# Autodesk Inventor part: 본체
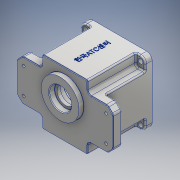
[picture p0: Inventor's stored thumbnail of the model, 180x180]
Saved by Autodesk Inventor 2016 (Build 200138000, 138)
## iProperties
Created: 2017-01
Part Number: 본체
Material: 알루미늄 6061
Document SubType Name: Modeling
Designer: Owner
Mass: 876.679 g
Surface Area: 765.057 cm^2
Volume: 324.696 cm^3
Density: 2.7 g/cm^3
Appearance: 알루미늄 - 평지
Author: Owner
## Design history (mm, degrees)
sketch "스케치1"
  geometry: L1 (70, -30)-(-70, -30); L2 (-70, -30)-(-70, 30); L3 (-70, 30)-(70, 30); L4 (70, 30)-(70, -30); L5 (70, -30)-(-70, 30); L6 (-70, -30)-(70, 30); 1 further point
  constraints: 12 end point, 2 midpoint, 2 parallel, 1 horizontal, 1 perpendicular
  dimensions: "d0" = 140 distance of L2.end L3.end; "d1" = 60 distance of L1.end L2.end
extrude "돌출1" new body sketch "스케치1" distance "d2" = 13; taper "d3" = 0 deg
sketch "스케치2"
  geometry: L1 (-47, -47)-(47, -47); L2 (47, -47)-(47, 47); L3 (47, 47)-(-47, 47); L4 (-47, 47)-(-47, -47); L5 (-47, -47)-(47, 47); L6 (47, -47)-(-47, 47); 1 further point
  constraints: 12 end point, 2 midpoint, 2 parallel, 1 horizontal, 1 perpendicular
  dimensions: "d4" = 94 distance of L3.end L2.end; "d5" = 94 distance of L2.end L1.end
extrude "돌출2" join sketch "스케치2" distance "d6" = 80; taper "d7" = 0 deg
sketch "스케치3"
  geometry: L1 (-47, 30)-(-33, 30); L2 (-33, 30)-(-33, 47); L3 (-33, 47)-(-47, 47); L4 (-47, 47)-(-47, 30); L5 (-47, 30)-(-33, 47); L6 (-33, 30)-(-47, 47); 3 further points
  constraints: 12 end point, 2 midpoint, 2 parallel, 1 coincident, 1 horizontal, 1 perpendicular
  dimensions: "d8" = 14 distance of L2.end L3.end; "d9" = 17 distance of L3.end L1.start
extrude "돌출3" cut sketch "스케치3" distance "d10" = 70; taper "d11" = 0 deg
sketch "스케치4"
  geometry: L1 (0, 0)-(80, 0); L2 (80, -47)-(80, 47) reference; L3 (80, 0)-(80, 43); L4 (71, 43)-(71, 40); L5 (71, 40)-(9, 40); L6 (9, 40)-(9, 0); L7 (71, 43)-(80, 43)
  constraints: 12 end point, 3 perpendicular, 2 point on line, 1 midpoint
  dimensions: "d12" = 86 diameter of L7 L1; "d13" = 80 diameter of L5 L1; "d14" = 9 distance of L4.start L3.end; "d15" = 71 distance between parallel lines of L2 L6
revolve "회전2" sketch "스케치4" stored, may be unused: angle "d17" = 90 deg
sketch "스케치5"
  geometry: A1 r 21 centre (0, -11) between (-8.978, 7.984) and (8.978, 7.984); A2 r 15 centre (0, 20) between (8.978, 7.984) and (-8.978, 7.984); 1 further point
  constraints: 4 point on circle, 2 centre point, 2 vertical alignment
  dimensions: "d18" = 11 distance of A1.centre point (0, 0); "d19" = 20 distance of point (0, 0) A2.centre; "d20" = 42 diameter of A1; "d21" = 30 diameter of A2
extrude "돌출4" join sketch "스케치5" distance "d22" = 7; taper "d23" = 0 deg
sketch "스케치6"
  geometry: A1 r 4 centre (36, 0) between (35.852, 3.997) and (35.852, -3.997); A2 r 40 centre (0, 0) between (39.148, -8.214) and (39.148, 8.214) reference; A3 r 3.5 centre (35.722, -7.495) between (39.148, -8.214) and (35.852, -3.997); A4 r 3.5 centre (35.722, 7.495) between (35.852, 3.997) and (39.148, 8.214); 1 further point
  constraints: 8 point on circle, 4 tangent, 3 centre point, 1 horizontal alignment
  dimensions: "d24" = 8 diameter of A1; "d25" = 36 distance of point (0, 0) A1.centre; "d28" = 7 diameter of A3; "d29" = 7 diameter of A4
extrude "돌출6" join sketch "스케치6" stored distance "d30" = 7; taper "d31" = 0 deg
hole "구멍1" diameter "d34" = 19; stored, may be unused: countersink angle "d38" = 90 deg, drill point angle "d40" = 0 deg; dims "d32" = 10, "d33" = 10, "d35" = 6, "d36" = 22, "d37" = 7, "d39" = 8
hole "구멍2" diameter "d43" = 25; stored, may be unused: countersink angle "d47" = 90 deg, drill point angle "d49" = 0 deg; dims "d41" = 10, "d42" = 10, "d44" = 6, "d45" = 35, "d46" = 10, "d48" = 8
sketch "스케치7"
  geometry: C1 r 27.5 at (0, 11); C2 r 12.5 at (0, 11) reference; 1 further point
  constraints: 1 centre point, 1 concentric
  dimensions: "d50" = 55 diameter of C1
extrude "돌출7" join sketch "스케치7" distance "d51" = 7; taper "d52" = 0 deg
hole "구멍3" diameter "d55" = 32; stored, may be unused: countersink angle "d59" = 90 deg, drill point angle "d61" = 0 deg; dims "d56" = 6, "d57" = 35, "d58" = 10, "d60" = 8, "d126" = 10, "d127" = 10
fillet "모깎기1" dims "d62" = 8
sketch "스케치8"
  geometry: 2 further points
  dimensions: "d63" = 40 horizontal distance of point (40, 40) point (0, 0); "d64" = 40 horizontal distance of point (0, 0) point (40, 40)
hole "구멍4" sketch "스케치8" at (40, 40) diameter "d65" = 7; stored, may be unused: countersink angle "d69" = 90 deg, drill point angle "d71" = 0 deg; dims "d66" = 6, "d67" = 35, "d68" = 10, "d70" = 7
sketch "스케치9"
  geometry: 2 further points
  dimensions: "d78" = 19 vertical distance of point (0, 0) point (60, 19); "d79" = 60 horizontal distance of point (0, 0) point (60, 19)
hole "구멍5" sketch "스케치9" at (60, 19) diameter "d80" = 4; stored, may be unused: countersink angle "d84" = 90 deg, drill point angle "d86" = 0 deg; dims "d81" = 6, "d82" = 10, "d83" = 4, "d85" = 7
chamfer "모따기1" distance "d93" = 1; stored, may be unused: second distance "d94" = 2, angle "d95" = 45 deg
hole "구멍6" diameter "d98" = 3.242; stored, may be unused: countersink angle "d102" = 90 deg, drill point angle "d104" = 118 deg; dims "d96" = 10, "d97" = 10, "d99" = 7, "d100" = 10, "d101" = 4, "d103" = 9
fillet "모깎기2" dims "d105" = 3
fillet "모깎기3" dims "d106" = 2
fillet "모깎기4" dims "d107" = 2
fillet "모깎기5" dims "d108" = 0.3
chamfer "모따기2" distance "d109" = 1; stored, may be unused: second distance "d110" = 2, angle "d111" = 45 deg
chamfer "모따기3" distance "d112" = 8; stored, may be unused: second distance "d113" = 2, angle "d114" = 45 deg
fillet "모깎기6" dims "d115" = 5
fillet "모깎기7" dims "d116" = 5
fillet "모깎기9" dims "d118" = 2
fillet "모깎기10" dims "d119" = 2
fillet "모깎기8" dims "d117" = 2
sketch "스케치10"
  geometry: L1 (-31, -47)-(31, -47) reference; L2 (33, -45)-(33, -35) reference; L3 (38, -30)-(59.929, -30) reference; L4 (68.536, -23.464)-(63.464, -28.536) reference; L5 (70, -19.929)-(70, 19.929) reference; L6 (63.464, 28.536)-(68.536, 23.464) reference; L7 (59.929, 30)-(38, 30) reference; L8 (33, 35)-(33, 45) reference; L9 (31, 47)-(-31, 47) reference; L10 (-33, 45)-(-33, 35) reference; L11 (-38, 30)-(-59.929, 30) reference; L12 (-68.536, 23.464)-(-63.464, 28.536) reference; L13 (-70, 19.929)-(-70, -19.929) reference; L14 (-63.464, -28.536)-(-68.536, -23.464) reference; L15 (-59.929, -30)-(-38, -30) reference; L16 (-33, -35)-(-33, -45) reference; L17 (-31, 46)-(31, 46); L18 (32, 45)-(32, 35); L19 (38, 29)-(59.929, 29); L20 (62.757, 27.828)-(67.828, 22.757); L21 (69, 19.929)-(69, -19.929); L22 (67.828, -22.757)-(62.757, -27.828); L23 (59.929, -29)-(38, -29); L24 (32, -35)-(32, -45); L25 (31, -46)-(-31, -46); L26 (-32, -45)-(-32, -35); L27 (-38, -29)-(-59.929, -29); L28 (-62.757, -27.828)-(-67.828, -22.757); L29 (-69, -19.929)-(-69, 19.929); L30 (-67.828, 22.757)-(-62.757, 27.828); L31 (-59.929, 29)-(-38, 29); L32 (-32, 35)-(-32, 45); C1 r 2 at (60, -19) reference; C2 r 2 at (-60, -19) reference; C3 r 2 at (60, 19) reference; C4 r 2 at (-60, 19) reference; C5 r 27.8 at (0, 11) reference; A1 r 2 centre (-31, -45) between (-33, -45) and (-31, -47) reference; A2 r 2 centre (31, -45) between (31, -47) and (33, -45) reference; A3 r 5 centre (38, -35) between (38, -30) and (33, -35) reference; A4 r 5 centre (59.929, -25) between (59.929, -30) and (63.464, -28.536) reference; A5 r 5 centre (65, -19.929) between (68.536, -23.464) and (70, -19.929) reference; A6 r 5 centre (65, 19.929) between (70, 19.929) and (68.536, 23.464) reference; A7 r 5 centre (59.929, 25) between (63.464, 28.536) and (59.929, 30) reference; A8 r 5 centre (38, 35) between (33, 35) and (38, 30) reference; A9 r 2 centre (31, 45) between (33, 45) and (31, 47) reference; A10 r 2 centre (-31, 45) between (-31, 47) and (-33, 45) reference; A11 r 5 centre (-38, 35) between (-38, 30) and (-33, 35) reference; A12 r 5 centre (-59.929, 25) between (-59.929, 30) and (-63.464, 28.536) reference; A13 r 5 centre (-65, 19.929) between (-68.536, 23.464) and (-70, 19.929) reference; A14 r 5 centre (-65, -19.929) between (-70, -19.929) and (-68.536, -23.464) reference; A15 r 5 centre (-59.929, -25) between (-63.464, -28.536) and (-59.929, -30) reference; A16 r 5 centre (-38, -35) between (-33, -35) and (-38, -30) reference; A17 r 1 centre (31, 45) between (32, 45) and (31, 46); A18 r 6 centre (38, 35) between (32, 35) and (38, 29); A19 r 4 centre (59.929, 25) between (62.757, 27.828) and (59.929, 29); A20 r 4 centre (65, 19.929) between (69, 19.929) and (67.828, 22.757); A21 r 4 centre (65, -19.929) between (67.828, -22.757) and (69, -19.929); A22 r 4 centre (59.929, -25) between (59.929, -29) and (62.757, -27.828); A23 r 6 centre (38, -35) between (38, -29) and (32, -35); A24 r 1 centre (31, -45) between (31, -46) and (32, -45); A25 r 1 centre (-31, -45) between (-32, -45) and (-31, -46); A26 r 6 centre (-38, -35) between (-32, -35) and (-38, -29); A27 r 4 centre (-59.929, -25) between (-62.757, -27.828) and (-59.929, -29); A28 r 4 centre (-65, -19.929) between (-69, -19.929) and (-67.828, -22.757); A29 r 4 centre (-65, 19.929) between (-67.828, 22.757) and (-69, 19.929); A30 r 4 centre (-59.929, 25) between (-59.929, 29) and (-62.757, 27.828); A31 r 6 centre (-38, 35) between (-38, 29) and (-32, 35); A32 r 1 centre (-31, 45) between (-31, 46) and (-32, 45); 1 further point
  constraints: 32 end point, 32 point on circle, 16 centre point, 31 other
  dimensions: "d120" = 1 distance between parallel lines of L9 L17
extrude "돌출8" cut sketch "스케치10" distance "d121" = 1; taper "d122" = 0 deg
sketch "스케치11"
  geometry: L1 (0, 0)-(78, 0) reference; 2 further points
  constraints: 1 vertical alignment, 1 other
  dimensions: "d123" = 40 distance from line of L1 point (39, -40)
feature "엠보싱1" sketch "스케치11" dims "d8" = 14, "d9" = 17, "d124" = 0.5, "d125" = 0
node "솔리드1"
mirror "대칭1"
mirror "대칭2"
mirror "대칭3"
pattern_linear "직사각형 패턴1" dims "d74" = 80
pattern_linear "직사각형 패턴2" dims "d89" = 120, "d92" = 38
mirror "대칭4"
node "투영된 루프1"
